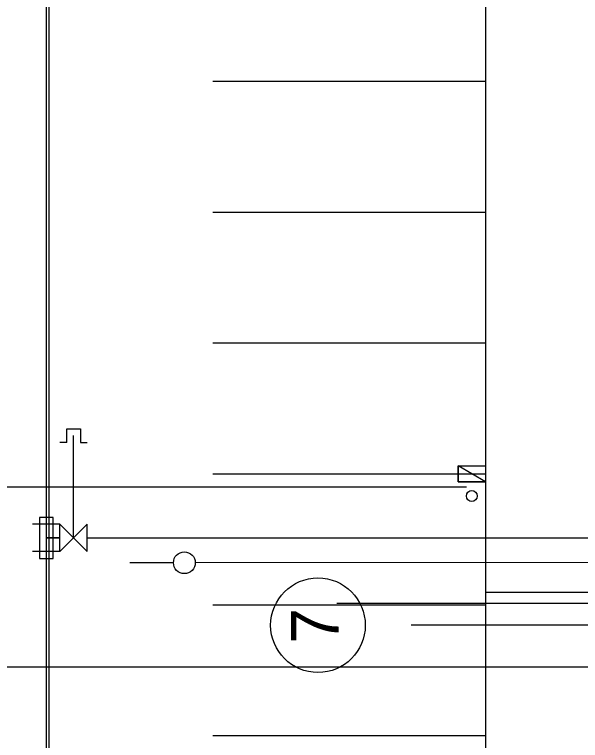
# Model space of a CAD drawing. Extents: x -264205 to -263659, y -1242401 to -1241986.
# Drawn here: x -263924.73 to -263914.35, y -1242121 to -1242107.68 of the extents above; entities that cross this region are included whole.
import ezdxf

# ---------------------------------------------------------------- set-up
doc = ezdxf.new("R2010")
doc.units = 0
for name, color, linetype in [('HESCON_OSI_STAVBY_KFA', 7, 'Continuous'), ('PROJEKT_TDZ_VODOROVNE', 7, 'Continuous'), ('RAM_NA_TLAC_2-2_1-250', 7, 'Continuous'), ('SITUACIA_DSP_2D', 7, 'Continuous')]:
    doc.layers.add(name, color=color, linetype=linetype)

msp = doc.modelspace()

# ---------------------------------------------------------------- linework, layer by layer
at = {"layer": 'HESCON_OSI_STAVBY_KFA'}
msp.add_line((-263792.653, -1242118.882), (-263917.453, -1242118.882), dxfattribs=at)
msp.add_circle((-263919.163, -1242118.883), 0.867, dxfattribs=at)
at = {"layer": 'PROJEKT_TDZ_VODOROVNE'}
for p, q in [((-263924.088, -1242241.458), (-263924.093, -1242087.307)), ((-263916.093, -1242087.308), (-263916.093, -1242141.207)), ((-263921.093, -1242108.907), (-263916.093, -1242108.907)), ((-263921.093, -1242111.307), (-263916.093, -1242111.307)), ((-263921.093, -1242113.707), (-263916.093, -1242113.707)), ((-263921.093, -1242116.107), (-263916.093, -1242116.107)), ((-263921.093, -1242118.507), (-263916.093, -1242118.507)), ((-263921.093, -1242120.907), (-263916.093, -1242120.907))]:
    msp.add_line(p, q, dxfattribs=at)
at = {"layer": 'RAM_NA_TLAC_2-2_1-250'}
msp.add_lwpolyline([(-263982.395, -1242045.402), (-263692.395, -1242045.402), (-263692.395, -1242119.652), (-263982.395, -1242119.652)], close=True, dxfattribs=at)
at = {"layer": 'SITUACIA_DSP_2D'}
for p, q in [((-263924.143, -1242082.64), (-263924.143, -1242185.14)), ((-263923.768, -1242115.532), (-263923.768, -1242115.282)), ((-263923.768, -1242115.282), (-263923.518, -1242115.282)), ((-263923.518, -1242115.282), (-263923.518, -1242115.532)), ((-263923.643, -1242117.282), (-263923.643, -1242115.407)), ((-263923.768, -1242115.532), (-263923.893, -1242115.532)), ((-263923.518, -1242115.532), (-263923.393, -1242115.532)), ((-263916.593, -1242116.252), (-263916.593, -1242115.962)), ((-263916.593, -1242115.962), (-263916.093, -1242115.962)), ((-263916.093, -1242116.252), (-263916.593, -1242115.962)), ((-263916.093, -1242116.252), (-263916.593, -1242115.962)), ((-263916.593, -1242115.962), (-263916.593, -1242116.252)), ((-263916.093, -1242115.962), (-263916.093, -1242116.252)), ((-263916.443, -1242116.352), (-263925.797, -1242116.352)), ((-263916.093, -1242116.252), (-263916.593, -1242116.252)), ((-263916.593, -1242116.252), (-263916.093, -1242116.252)), ((-263924.018, -1242116.907), (-263924.268, -1242116.907)), ((-263924.268, -1242116.907), (-263924.268, -1242117.657)), ((-263924.018, -1242117.657), (-263924.018, -1242116.907)), ((-263923.893, -1242117.032), (-263924.393, -1242117.032)), ((-263923.893, -1242117.532), (-263923.893, -1242117.032)), ((-263923.893, -1242117.032), (-263923.393, -1242117.532)), ((-263923.393, -1242117.032), (-263923.893, -1242117.532)), ((-263923.393, -1242117.532), (-263923.393, -1242117.032)), ((-263924.143, -1242117.282), (-263923.893, -1242117.282)), ((-263923.893, -1242117.282), (-263924.143, -1242117.282)), ((-263923.393, -1242117.282), (-263906.493, -1242117.282)), ((-263923.893, -1242117.532), (-263924.393, -1242117.532)), ((-263924.268, -1242117.657), (-263924.018, -1242117.657)), ((-263921.812, -1242117.737), (-263922.612, -1242117.737)), ((-263903.343, -1242117.732), (-263921.412, -1242117.737)), ((-263893.618, -1242118.282), (-263916.093, -1242118.282)), ((-263916.093, -1242118.282), (-263916.093, -1242175.482)), ((-263908.718, -1242118.482), (-263918.819, -1242118.482))]:
    msp.add_line(p, q, dxfattribs=at)
for centre, radius in [((-263916.343, -1242116.514), 0.1), ((-263921.612, -1242117.737), 0.2)]:
    msp.add_circle(centre, radius, dxfattribs=at)

# ---------------------------------------------------------------- texts
at = {"layer": 'HESCON_OSI_STAVBY_KFA'}
msp.add_text('7', height=0.875, rotation=90, dxfattribs=at).set_placement((-263918.782, -1242119.223))

doc.saveas('drawing.dxf')
